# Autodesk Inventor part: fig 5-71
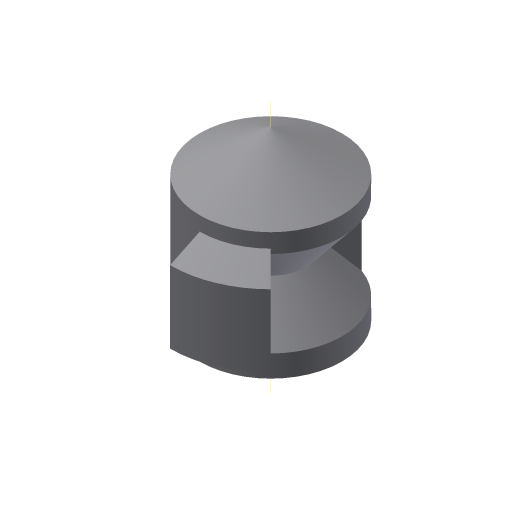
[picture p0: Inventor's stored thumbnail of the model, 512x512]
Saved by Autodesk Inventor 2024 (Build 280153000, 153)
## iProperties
Created: 2004-05
Part Number: fig 5-71
Document SubType Name: Modeling
Designer: CADCIM Technologies
Manufacturer: Standard
Standards Organization: Custom
Density: 1 g/cm^3
Material: Generic
Appearance: Default
Author: CADCIM Technologies
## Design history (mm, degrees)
sketch "Sketch1"
  geometry: L1 (0, -21.51)-(0, 21.51); L2 (0, 21.51)-(-14.639, 13.059); L3 (-14.639, 13.059)-(-14.639, -13.059); L4 (-14.639, -13.059)-(0, -21.51); 2 further points
  constraints: 8 end point, 1 coincident, 1 equal length, 1 midpoint, 1 parallel, 1 vertical, 1 other
  dimensions: "d3" = 120 deg angle of L4 L3
revolve "Revolution1" sketch "Sketch1" stored, may be unused: angle "d0" = 90 deg
workaxis "Work Axis1"
sketch "Sketch2"
  geometry: L1 (-15.658, 10.423)-(-7.144, 0); L2 (-7.144, 0)-(-15.658, -9.738); L3 (-15.658, -9.738)-(-15.658, 10.423); L4 (0, -25.812)-(0, 34.416) reference
  constraints: 6 end point, 1 vertical
revolve "Revolution2" sketch "Sketch2" stored, may be unused: angle "d4" = 140 deg
sketch "Sketch3"
  geometry: L1 (-14.955, 9.983)-(-20.736, 7.191); L2 (-20.736, 7.191)-(-20.736, -7.686); L3 (-20.736, -7.686)-(-15, -10.57); L4 (0, -25.812)-(0, 34.416) reference
  constraints: 6 end point, 1 equal length, 1 vertical
revolve "Revolution4" sketch "Sketch3" stored, may be unused: angle "d9" = 45 deg
body "Solid1"
other parameters: "d10" = 45 deg
